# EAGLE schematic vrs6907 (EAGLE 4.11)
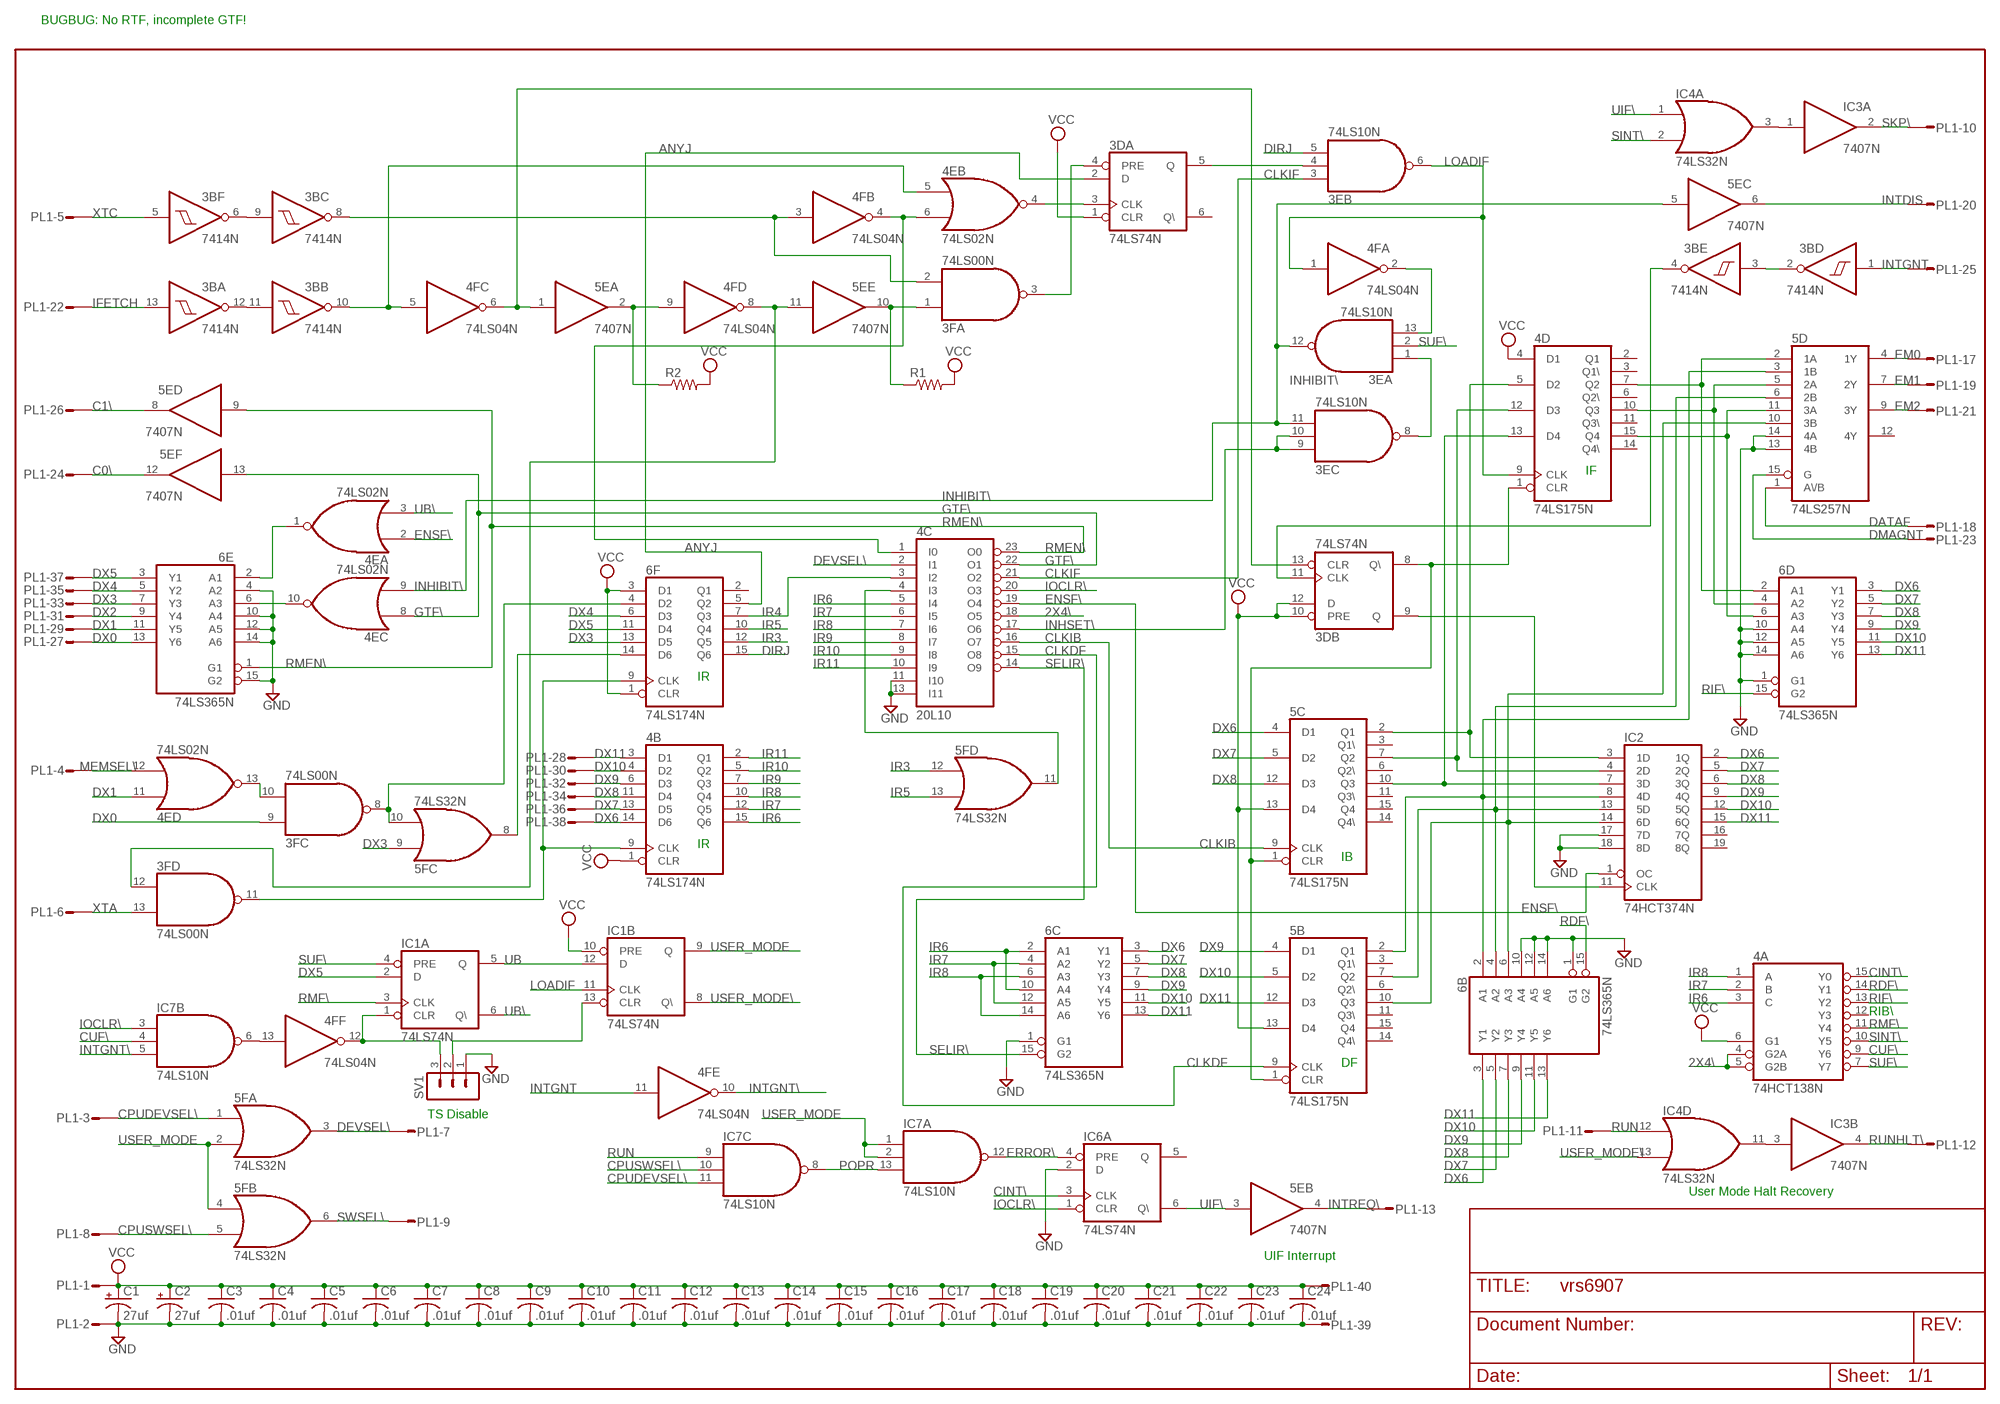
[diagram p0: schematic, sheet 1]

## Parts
3B  7414N  [DIL14]
3D  74LS74N  [DIL14]
3E  74LS10N  [DIL14]
3F  74LS00N  [DIL14]
4A  74HCT138N  [DIL16]
4B  74LS174N  [DIL16]
4C  20L10  [DIL24-3]
4D  74LS175N  [DIL16]
4E  74LS02N  [DIL14]
4F  74LS04N  [DIL14]
5B  74LS175N  [DIL16]
5C  74LS175N  [DIL16]
5D  74LS257N  [DIL16]
5E  7407N  [DIL14]
5F  74LS32N  [DIL14]
6B  74LS365N  [DIL16]
6C  74LS365N  [DIL16]
6D  74LS365N  [DIL16]
6E  74LS365N  [DIL16]
6F  74LS174N  [DIL16]
C1  27uf  CPOL-USE22-6AXIAL  [E22-6]
C2  27uf  CPOL-USE22-6AXIAL  [E22-6]
C3  .01uf  C-US050-025X075  [C050-025X075]
C4  .01uf  C-US050-025X075  [C050-025X075]
C5  .01uf  C-US050-025X075  [C050-025X075]
C6  .01uf  C-US050-025X075  [C050-025X075]
C7  .01uf  C-US050-025X075  [C050-025X075]
C8  .01uf  C-US050-025X075  [C050-025X075]
C9  .01uf  C-US050-025X075  [C050-025X075]
C10  .01uf  C-US050-025X075  [C050-025X075]
C11  .01uf  C-US050-025X075  [C050-025X075]
C12  .01uf  C-US050-025X075  [C050-025X075]
C13  .01uf  C-US050-025X075  [C050-025X075]
C14  .01uf  C-US050-025X075  [C050-025X075]
C15  .01uf  C-US050-025X075  [C050-025X075]
C16  .01uf  C-US050-025X075  [C050-025X075]
C17  .01uf  C-US050-025X075  [C050-025X075]
C18  .01uf  C-US050-025X075  [C050-025X075]
C19  .01uf  C-US050-025X075  [C050-025X075]
C20  .01uf  C-US050-025X075  [C050-025X075]
C21  .01uf  C-US050-025X075  [C050-025X075]
C22  .01uf  C-US050-025X075  [C050-025X075]
C23  .01uf  C-US050-025X075  [C050-025X075]
C24  .01uf  C-US050-025X075  [C050-025X075]
IC1  74LS74N  [DIL14]
IC2  74HCT374N  [DIL20]
IC3  7407N  [DIL14]
IC4  74LS32N  [DIL14]
IC6  74LS74N  [DIL14]
IC7  74LS10N  [DIL14]
PL1  40VS  [40V]
R1  R-US_0207/10  [0207/10]
R2  R-US_0207/10  [0207/10]
SV1  MA03-1  [MA03-1]

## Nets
2X4\: 4A.4(G2A) 4A.5(G2B) 4C.18(O5)
ANYJ: 3D.2(A:D) 6F.5(Q2)
C0\: 5E.12(F:O) PL1.24
C1\: 5E.8(D:O) PL1.26
CINT\: 4A.15(Y0) IC6.3(A:CLK)
CLKDF: 4C.15(O8) 5B.9(CLK)
CLKIB: 4C.16(O7) 5C.9(CLK)
CLKIF: 3E.3(B:I0) 4C.21(O2)
CPUDEVSEL\: 5F.1(A:I0) IC7.11(C:I2) PL1.3
CPUSWSEL\: 5F.5(B:I1) IC7.10(C:I1) PL1.8
CUF\: 4A.9(Y6) IC7.4(B:I1)
DATAF: 5D.1(A\/B) PL1.18
DEVSEL\: 4C.2(I1) 5F.3(A:O) PL1.7
DIRJ: 3E.5(B:I2) 6F.15(Q6)
DMAGNT: 5D.15(G) PL1.23
DX0: 3F.9(C:I0) 6E.13(Y6) PL1.27
DX1: 4E.11(D:I0) 6E.11(Y5) PL1.29
DX2: 6E.9(Y4) PL1.31
DX3: 5F.9(C:I0) 6E.7(Y3) 6F.13(D5) PL1.33
DX4: 6E.5(Y2) 6F.6(D3) PL1.35
DX5: 6E.3(Y1) 6F.11(D4) IC1.2(A:D) PL1.37
DX6: 4B.14(D6) 5C.4(D1) 6B.3(Y1) 6C.3(Y1) 6D.3(Y1) IC2.2(1Q) PL1.38
DX7: 4B.13(D5) 5C.5(D2) 6B.5(Y2) 6C.5(Y2) 6D.5(Y2) IC2.5(2Q) PL1.36
DX8: 4B.11(D4) 5C.12(D3) 6B.7(Y3) 6C.7(Y3) 6D.7(Y3) IC2.6(3Q) PL1.34
DX9: 4B.6(D3) 5B.4(D1) 6B.9(Y4) 6C.9(Y4) 6D.9(Y4) IC2.9(4Q) PL1.32
DX10: 4B.4(D2) 5B.5(D2) 6B.11(Y5) 6C.11(Y5) 6D.11(Y5) IC2.12(5Q) PL1.30
DX11: 4B.3(D1) 5B.12(D3) 6B.13(Y6) 6C.13(Y6) 6D.13(Y6) IC2.15(6Q) PL1.28
EM0: 5D.4(1Y) PL1.17
EM1: 5D.7(2Y) PL1.19
EM2: 5D.9(3Y) PL1.21
ENSF\: 4C.19(O4) 4E.2(A:I0) IC2.1(OC)
ERROR\: IC6.4(A:PRE) IC7.12(A:O)
GND: 4C.11(I10) 4C.13(I11) 5D.13(4B) 5D.14(4A) 6B.1(G1) 6B.10(A4) 6B.12(A5) 6B.14(A6) 6C.1(G1) 6D.1(G1) 6D.10(A4) 6D.12(A5) 6D.14(A6) 6E.4(A2) 6E.10(A4) 6E.12(A5) 6E.14(A6) 6E.15(G2) C1.- C2.- C3.2 C4.2 C5.2 C6.2 C7.2 C8.2 C9.2 C10.2 C11.2 C12.2 C13.2 C14.2 C15.2 C16.2 C17.2 C18.2 C19.2 C20.2 C21.2 C22.2 C23.2 C24.2 IC2.17(7D) IC2.18(8D) IC6.2(A:D) PL1.2 PL1.39 SV1.1
GTF\: 4C.22(O1) 4E.8(C:I0) 5E.13(F:I)
IFETCH: 3B.13(A:I) PL1.22
INHIBIT\: 3E.11(C:I2) 3E.12(A:O) 4E.9(C:I1) 5E.5(C:I)
INHSET\: 3E.9(C:I0) 3E.10(C:I1) 4C.17(O6)
INTDIS: 5E.6(C:O) PL1.20
INTGNT: 3B.1(D:I) 4F.11(E:I) PL1.25
INTGNT\: 4F.10(E:O) IC7.5(B:I2)
INTREQ\: 5E.4(B:O) PL1.13
IOCLR\: 4C.20(O3) IC6.1(A:CLR) IC7.3(B:I0)
IR3: 5F.12(D:I0) 6F.12(Q5)
IR4: 4C.3(I2) 6F.7(Q3)
IR5: 5F.13(D:I1) 6F.10(Q4)
IR6: 4A.3(C) 4B.15(Q6) 4C.5(I4) 6C.2(A1) 6C.10(A4)
IR7: 4A.2(B) 4B.12(Q5) 4C.6(I5) 6C.4(A2) 6C.12(A5)
IR8: 4A.1(A) 4B.10(Q4) 4C.7(I6) 6C.6(A3) 6C.14(A6)
IR9: 4B.7(Q3) 4C.8(I7)
IR10: 4B.5(Q2) 4C.9(I8)
IR11: 4B.2(Q1) 4C.10(I9)
LOADIF: 3E.6(B:O) 4D.9(CLK) 4F.1(A:I) IC1.11(B:CLK)
LOADIR: 3F.11(D:O) 4B.9(CLK) 6F.9(CLK)
MEMSEL\: 4E.12(D:I1) PL1.4
N$1: 3B.11(B:I) 3B.12(A:O)
N$2: 3B.6(F:O) 3B.9(C:I)
N$3: 3B.8(C:O) 3F.2(A:I1) 4F.3(B:I)
N$4: 3B.10(B:O) 4E.5(B:I0) 4F.5(C:I)
N$5: 3D.13(B:CLR) 4F.6(C:O) 5E.1(A:I)
N$6: 3D.5(A:Q) 3E.4(B:I1)
N$7: 3F.1(A:I0) 5E.10(E:O) R1.1
N$8: 3F.12(D:I0) 4F.8(D:O) 5E.11(E:I)
N$9: 4F.9(D:I) 5E.2(A:O) R2.1
N$10: 4C.1(I0) 4E.6(B:I1) 4F.4(B:O)
N$11: 3D.3(A:CLK) 4E.4(B:O)
N$12: 3D.4(A:PRE) 3F.3(A:O)
N$13: IC3.3(B:I) IC4.11(D:O)
N$14: 3F.10(C:I1) 4E.13(D:O)
N$15: 4E.10(C:O) 6E.6(A3)
N$16: 4F.12(F:O) IC1.1(A:CLR) SV1.3
N$17: 4E.1(A:O) 6E.2(A1)
N$18: 3F.8(C:O) 5F.10(C:I1) 6F.4(D2)
N$19: 5F.8(C:O) 6F.14(D6)
N$20: 4C.4(I3) 5F.11(D:O)
N$24: IC1.13(B:CLR) SV1.2
N$25: IC3.1(A:I) IC4.3(A:O)
N$26: 4F.13(F:I) IC7.6(B:O)
N$45: 4D.7(Q2) 5D.2(1A) 6D.2(A1)
N$46: 4D.15(Q4) 5D.11(3A) 6D.6(A3)
N$47: 4D.10(Q3) 5D.5(2A) 6D.4(A2)
N$48: 3D.8(B:Q\) 4D.1(CLR) 5B.1(CLR) 5C.1(CLR)
N$50: 4D.5(D2) 5C.2(Q1) IC2.3(1D)
N$51: 4D.12(D3) 5C.7(Q2) IC2.4(2D)
N$52: 4D.13(D4) 5C.10(Q3) IC2.7(3D)
N$53: 5B.2(Q1) 5D.3(1B) 6B.2(A1) IC2.8(4D)
N$54: 5B.7(Q2) 5D.6(2B) 6B.4(A2) IC2.13(5D)
N$55: 5B.10(Q3) 5D.10(3B) 6B.6(A3) IC2.14(6D)
N$59: 3D.9(B:Q) IC2.11(CLK)
N$70: 3E.1(A:I0) 3E.8(C:O)
N$71: 3E.13(A:I2) 4F.2(A:O)
N$72: 3B.2(D:O) 3B.3(E:I)
N$74: 3B.4(E:O) 3D.11(B:CLK)
POPR: IC7.8(C:O) IC7.13(A:I2)
RDF\: 4A.14(Y1) 6B.15(G2)
RIF\: 4A.13(Y2) 6D.15(G2)
RMEN\: 4C.23(O0) 5E.9(D:I) 6E.1(G1)
RMF\: 4A.11(Y4) IC1.3(A:CLK)
RUN: IC4.12(D:I0) IC7.9(C:I0) PL1.11
RUNHLT\: IC3.4(B:O) PL1.12
SELIR\: 4C.14(O9) 6C.15(G2)
SINT\: 4A.10(Y5) IC4.2(A:I1)
SKP\: IC3.2(A:O) PL1.10
SUF\: 3E.2(A:I1) 4A.7(Y7) IC1.4(A:PRE)
SWSEL\: 5F.6(B:O) PL1.9
UB: IC1.5(A:Q) IC1.12(B:D)
UB\: 4E.3(A:I1) IC1.6(A:Q\)
UIF\: 5E.3(B:I) IC4.1(A:I0) IC6.6(A:Q\)
USER_MODE: 5F.2(A:I1) 5F.4(B:I0) IC1.9(B:Q) IC7.1(A:I0) IC7.2(A:I1)
USER_MODE\: IC1.8(B:Q\) IC4.13(D:I1)
VCC: 3D.1(A:CLR) 3D.10(B:PRE) 3D.12(B:D) 4A.6(G1) 4B.1(CLR) 4D.4(D1) 5B.13(D4) 5C.13(D4) 6F.1(CLR) 6F.3(D1) C1.+ C2.+ C3.1 C4.1 C5.1 C6.1 C7.1 C8.1 C9.1 C10.1 C11.1 C12.1 C13.1 C14.1 C15.1 C16.1 C17.1 C18.1 C19.1 C20.1 C21.1 C22.1 C23.1 C24.1 IC1.10(B:PRE) PL1.1 PL1.40 R1.2 R2.2
XTA: 3F.13(D:I1) PL1.6
XTC: 3B.5(F:I) PL1.5
Unconnected: 3D.6(A:Q\) 3F.4(B:I0) 3F.5(B:I1) 3F.6(B:O) 4A.12(Y3) 4D.2(Q1) 4D.3(Q1\) 4D.6(Q2\) 4D.11(Q3\) 4D.14(Q4\) 5B.3(Q1\) 5B.6(Q2\) 5B.11(Q3\) 5B.14(Q4\) 5B.15(Q4) 5C.3(Q1\) 5C.6(Q2\) 5C.11(Q3\) 5C.14(Q4\) 5C.15(Q4) 5D.12(4Y) 6F.2(Q1) IC2.16(7Q) IC2.19(8Q) IC3.5(C:I) IC3.6(C:O) IC3.8(D:O) IC3.9(D:I) IC3.10(E:O) IC3.11(E:I) IC3.12(F:O) IC3.13(F:I) IC4.4(B:I0) IC4.5(B:I1) IC4.6(B:O) IC4.8(C:O) IC4.9(C:I0) IC4.10(C:I1) IC6.5(A:Q) IC6.8(B:Q\) IC6.9(B:Q) IC6.10(B:PRE) IC6.11(B:CLK) IC6.12(B:D) IC6.13(B:CLR) PL1.14 PL1.15 PL1.16

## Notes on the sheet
- BUGBUG: No RTF, incomplete GTF!
- IF
- IR
- IR
- IB
- RIB\
- DF
- TS Disable
- User Mode Halt Recovery
- UIF Interrupt

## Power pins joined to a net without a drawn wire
GND: 3B.7(P:GND) 3D.7(P:GND) 3E.7(P:GND) 3F.7(P:GND) 4A.8(GND) 4B.8(GND) 4C.12(GND) 4D.8(GND) 4E.7(P:GND) 4F.7(P:GND) 5B.8(GND) 5C.8(GND) 5D.8(GND) 5E.7(P:GND) 5F.7(P:GND) 6B.8(GND) 6C.8(GND) 6D.8(GND) 6E.8(GND) 6F.8(GND) IC1.7(P:GND) IC2.10(GND) IC3.7(P:GND) IC4.7(P:GND) IC6.7(P:GND) IC7.7(P:GND)
VCC: 3B.14(P:VCC) 3D.14(P:VCC) 3E.14(P:VCC) 3F.14(P:VCC) 4A.16(VCC) 4B.16(VCC) 4C.24(VCC) 4D.16(VCC) 4E.14(P:VCC) 4F.14(P:VCC) 5B.16(VCC) 5C.16(VCC) 5D.16(VCC) 5E.14(P:VCC) 5F.14(P:VCC) 6B.16(VCC) 6C.16(VCC) 6D.16(VCC) 6E.16(VCC) 6F.16(VCC) IC1.14(P:VCC) IC2.20(VCC) IC3.14(P:VCC) IC4.14(P:VCC) IC6.14(P:VCC) IC7.14(P:VCC)

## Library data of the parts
3B = 74xx-jameco:74*14: Hex schmitt trigger INVERTER
3D IC1 IC6 = 74xx-jameco:74*74: Dual D type positive edge triggered FLIP FLOP, preset and clear
3E IC7 = 74xx-jameco:74*10: Triple 3-input NAND gate
3F = 74xx-jameco:74*00: Quad 2-input NAND gate
4A = 74xx-jameco:74*138: 3-line to 8-line DECODER/DEMULTIPLEXER
4B 6F = 74xx-jameco:74*174: Hex D type FLIP FLOP, clear
4C = pal:20L10: PAL
4D 5B 5C = 74xx-jameco:74*175: Qadruple D type FLIP FLOP, clear
4E = 74xx-jameco:74*02: Quad 2-input NOR gate
4F = 74xx-jameco:74*04: Hex INVERTER
5D = 74xx-jameco:74*257: Quadruple 2-to 1 line data SELECTOR/MULTIPLEXER
5E IC3 = 74xx-jameco:74*07: Hex BUFFER, open collector high-voltage output
5F IC4 = 74xx-jameco:74*32: Quad 2-input OR gate
6B 6C 6D 6E = 74xx-jameco:74*365: Hex BUS DRIVER, 3-state
C1 C2 = rcl:CPOL-US: POLARIZED CAPACITOR, American symbol
C3-C24 = rcl:C-US: CAPACITOR, American symbol
IC2 = 74xx-jameco:74*374: Octal D type transparent LATCH, edge triggered
PL1 = con-harting-v:40VS: CONNECTOR
R1 R2 = rcl:R-US_: RESISTOR, American symbol
SV1 = con-lstb:MA03-1: PIN HEADER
